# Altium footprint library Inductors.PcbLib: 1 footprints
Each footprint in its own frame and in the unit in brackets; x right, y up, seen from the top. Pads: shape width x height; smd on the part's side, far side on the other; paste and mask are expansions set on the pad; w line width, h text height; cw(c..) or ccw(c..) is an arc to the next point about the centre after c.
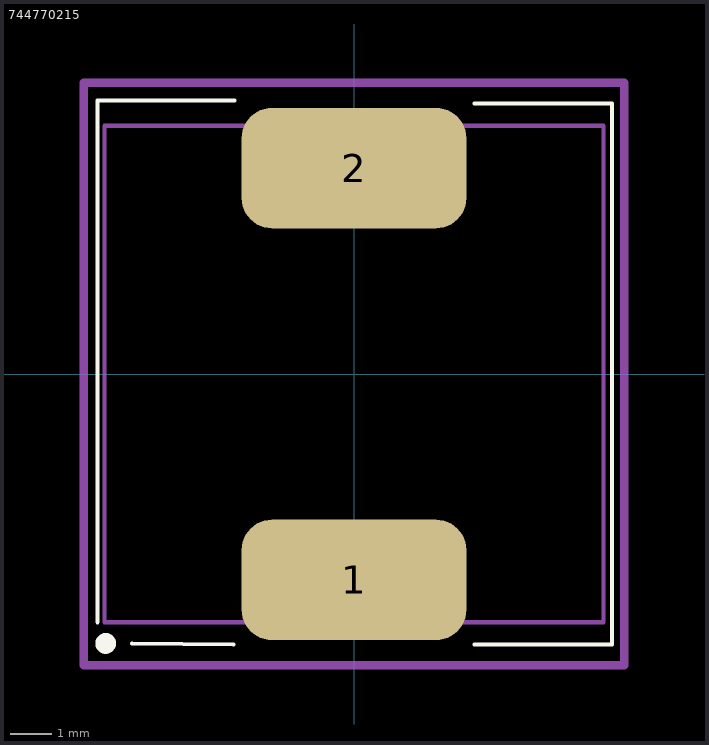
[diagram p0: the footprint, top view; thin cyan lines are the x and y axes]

## 744770215 [mm]
pads (2):
  rrect50% 5.4x2.9 smd: 1(0,-4.95) 2(0,4.95)
Top Overlay:
  circle w0.3: c-5.969,-6.477 r0.1
  lines w0.1: -6.17,-5.969 -6.17,6.576 -2.87,6.576 ; -5.334,-6.477 -2.9,-6.5 ; 2.9,-6.5 6.2,-6.5 6.2,6.5 2.9,6.5
Mechanical 13 (Mech13):
  lines w0.1: -6,-5.969 6,-5.969 6,5.969 -6,5.969 -6,-5.969
Component Courtyard:
  lines w0.2: -6.5,-7 6.5,-7 6.5,7 -6.5,7 -6.5,-7
3D body "Download_WE-PD_1280_STP (rev1).stp": height 7.26, standoff -0.2, extent -6,-6 6,6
